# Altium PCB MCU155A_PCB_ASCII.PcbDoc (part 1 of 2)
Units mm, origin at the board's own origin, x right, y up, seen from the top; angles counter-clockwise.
Board outline 32 x 29 mm, 4 copper layers (Top Layer, Layer 1, Layer 2, Bottom Layer), stack 1.567 mm thick; 102 components, 61 nets, 283 pads, 121 vias.
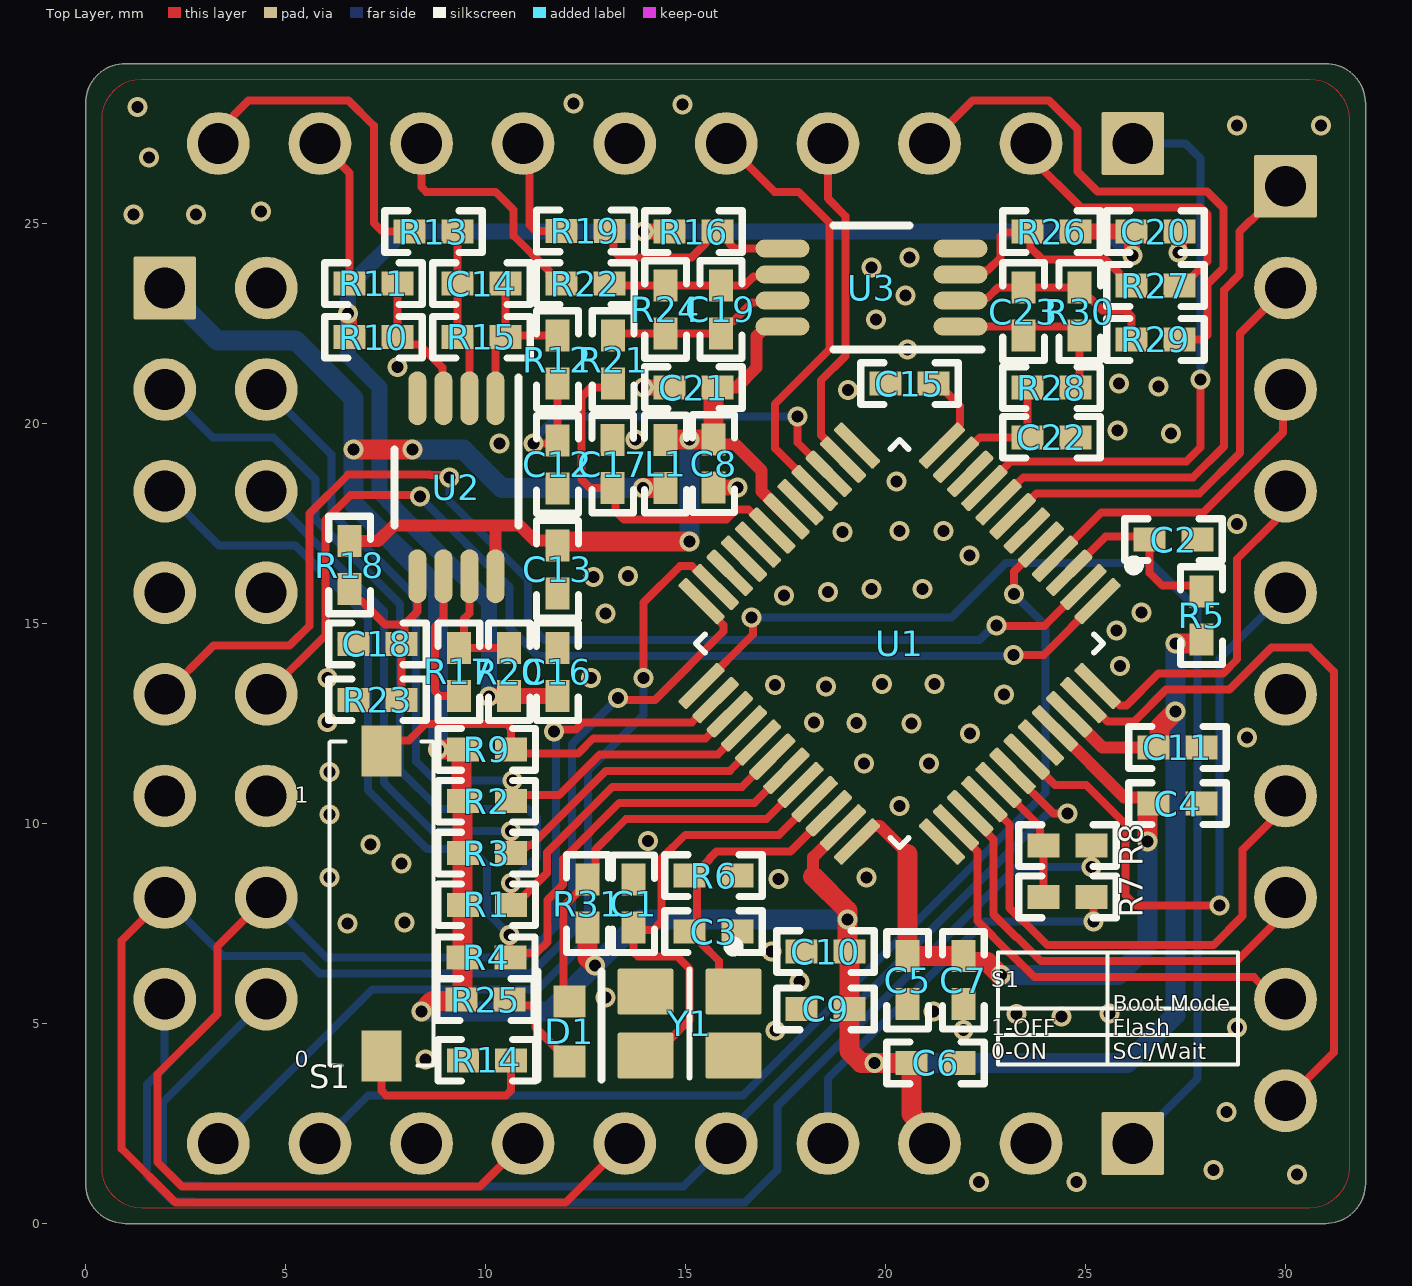
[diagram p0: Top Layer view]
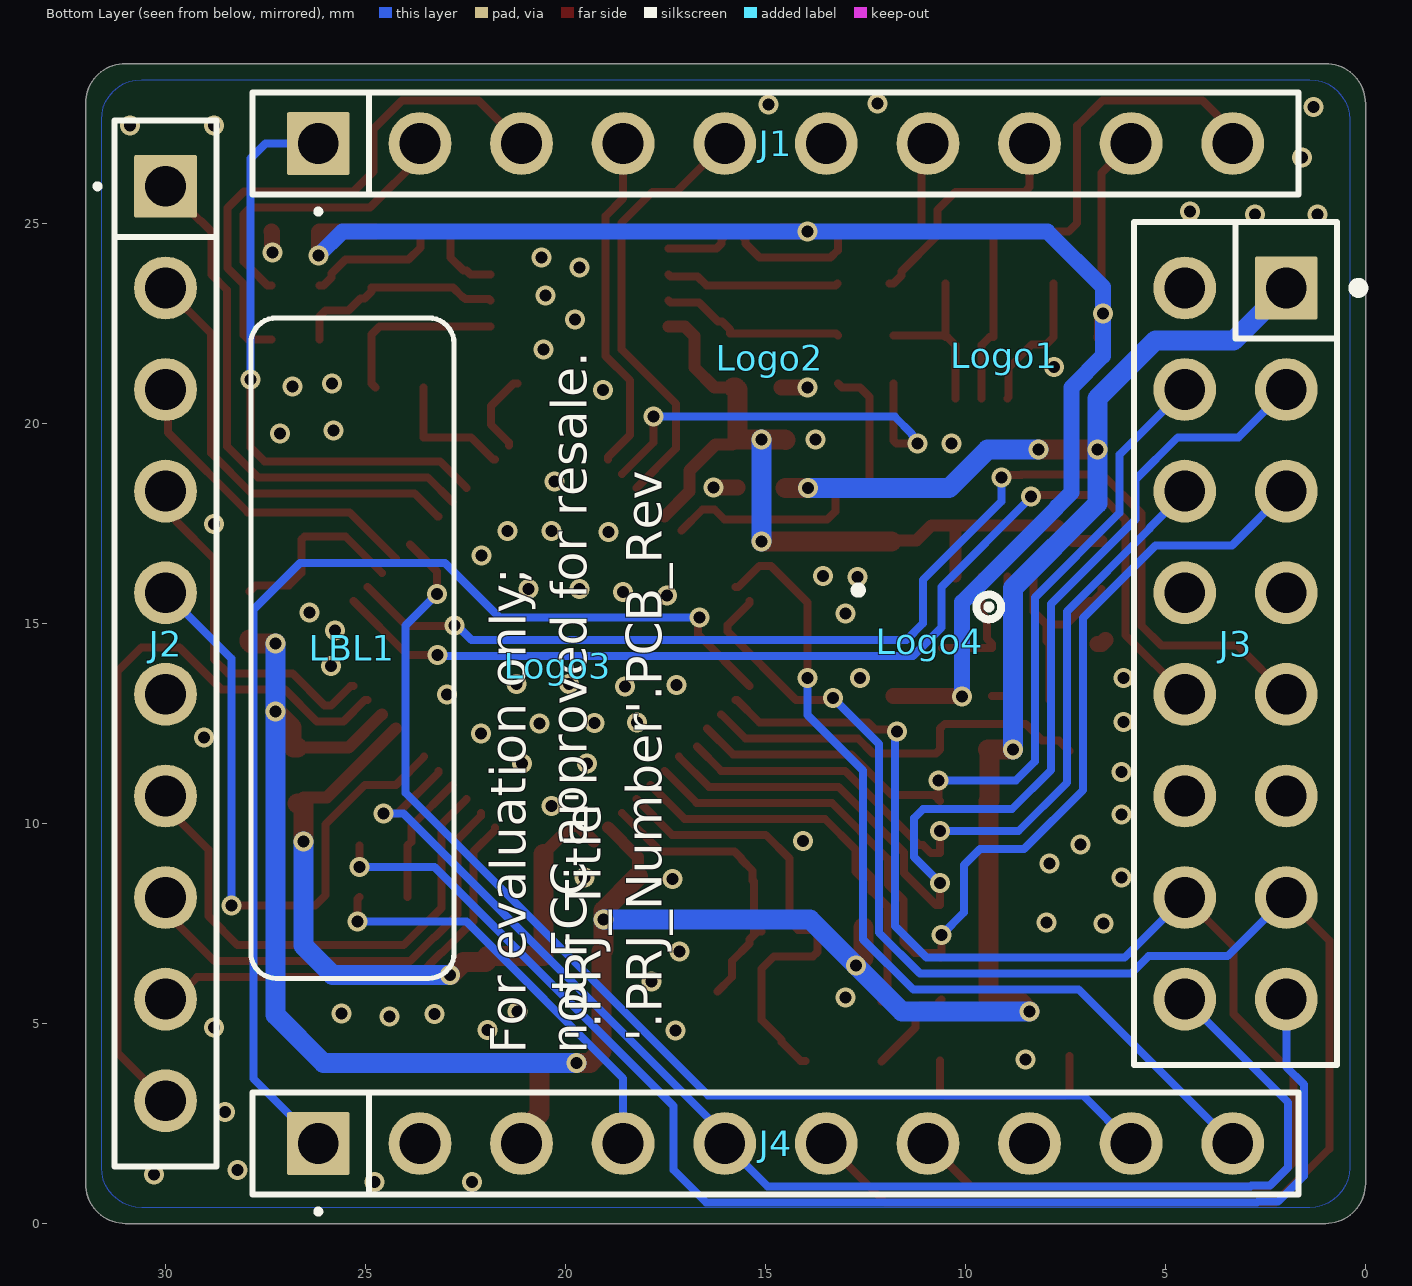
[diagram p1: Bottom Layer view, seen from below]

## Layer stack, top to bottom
Top Solder: solder mask 0.0102, Solder Resist, Dk 3.5
Top Layer: signal copper 0.035
Dielectric 1: prepreg 0.2184, PP-023, Dk 4.5
Layer 1: signal copper 0.035
Dielectric1: core 0.9906, Core-042, Dk 4.6
Layer 2: signal copper 0.035
Dielectric 2: prepreg 0.2184, PP-023, Dk 4.5
Bottom Layer: signal copper 0.035
Bottom Solder: solder mask 0.0102, Solder Resist, Dk 3.5

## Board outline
0,1 0,28 cw(c1,28) 1,29 31,29 cw(c31,28) 32,28 32,1 cw(c31,1) 31,0 1,0 cw(c1,1)

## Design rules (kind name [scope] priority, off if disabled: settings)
AcuteAngle [All] p0: scope1count=1 scope1_0_kind=Board scope1_0_value=Board scope2count=1 scope2_0_kind=Board scope2_0_value=Board commentlength=0 minimum=4.50000000000000E+0001
AcuteAngle [All] p1: minimum=4.50000000000000E+0001 checktracksonly=FALSE
AssemblyTestPointUsage [All] p0: scope1count=1 scope1_0_kind=Board scope1_0_value=Board scope2count=1 scope2_0_kind=Board scope2_0_value=Board commentlength=0
AssemblyTestPointUsage [All] p1: valid=2
AssemblyTestpoint [All] p0: scope1count=1 scope1_0_kind=Board scope1_0_value=Board scope2count=1 scope2_0_kind=Board scope2_0_value=Board commentlength=0
BoardOutlineClearance [All] p0 off: scope1count=1 scope1_0_kind=Board scope1_0_value=Board scope2count=1 scope2_0_kind=Board scope2_0_value=Board commentlength=172 gap=0 // Protel DXP Scope 1 Expression Was: OnCopper and Not InComponentClass('Logo') and not InComponentClass('FiducialMark') and not InRegion(1000,500,4000,800) and not InPoly
BoardOutlineClearance BoardOutlineClearance_Poly [All] p0 off: scope1count=1 scope1_0_kind=Board scope1_0_value=Board scope2count=1 scope2_0_kind=Board scope2_0_value=Board commentlength=58 gap=0 // Protel DXP Scope 1 Expression Was: OnCopper and IsPoly
BoardOutlineClearance BoardOutlineClearance_MountingHoles [All] p0 off: scope1count=1 scope1_0_kind=Board scope1_0_value=Board scope2count=1 scope2_0_kind=Board scope2_0_value=Board commentlength=86 gap=0 // Protel DXP Scope 1 Expression Was: OnCopper and InComponentClass('Mounting Holes')
BoardOutlineClearance BoardOutlineClearance_MountingHoles [OnCopper and InComponentClass('Mounting Holes')] p1: gap=0 ignorepadtopadclearanceinfootprint=FALSE
BoardOutlineClearance BoardOutlineClearance_Poly [OnCopper and IsPoly] p2: gap=0 ignorepadtopadclearanceinfootprint=FALSE
BoardOutlineClearance [OnCopper and Not InComponentClass('Logo') and not InComponentClass('FiducialMark') and not InRegion(1000,500,4000,800) and not InPoly] p3: gap=0 ignorepadtopadclearanceinfootprint=FALSE
Clearance Clearance_1 [All] p0 off: scope1count=1 scope1_0_kind=Board scope1_0_value=Board scope2count=1 scope2_0_kind=Board scope2_0_value=Board commentlength=160 gap=0.19 // Protel DXP Scope 1 Expression Was: (InComponent('J1') or InComponent('J2') or InComponent('J3') or InComponent('J4') ) and not HasFootprint('fiducial10-20')
Clearance [All] p0 off: scope1count=1 scope1_0_kind=Board scope1_0_value=Board scope2count=1 scope2_0_kind=Board scope2_0_value=Board commentlength=159 gap=0.2 // Protel DXP Scope 2 Expression Was: not HasFootprint('fiducial10-20') or (InComponent('J1') or InComponent('J2') or InComponent('J3') or InComponent('J4') )
Clearance SMTPadToTHHole [All] p0 off: scope1count=1 scope1_0_kind=Board scope1_0_value=Board scope2count=1 scope2_0_kind=Board scope2_0_value=Board commentlength=115 gap=0.15 // Protel DXP Scope 2 Expression Was: InSMTComponent and OnLayer('Bottom Layer') and not HasFootprint('TP_SM_1MM')
Clearance PB+ToPB- [All] p0: scope1count=1 scope1_0_kind=NetClass scope1_0_value=HV scope2count=1 scope2_0_kind=NetClass scope2_0_value=LV_Signal commentlength=0 gap=3
Clearance PB+ToACN [All] p0: scope1count=1 scope1_0_kind=NetClass scope1_0_value=V_BUS scope2count=1 scope2_0_kind=NetClass scope2_0_value=ACN commentlength=0 gap=1.5
Clearance PB+ToACL [All] p0: scope1count=1 scope1_0_kind=NetClass scope1_0_value=V_BUS scope2count=1 scope2_0_kind=NetClass scope2_0_value=ACL commentlength=0 gap=3
Clearance PB-ToACL [All] p0: scope1count=1 scope1_0_kind=NetClass scope1_0_value="LV Signal" scope2count=1 scope2_0_kind=NetClass scope2_0_value=ACL commentlength=0 gap=3
Clearance ISOToAll [All] p0 off: scope1count=1 scope1_0_kind=NetClass scope1_0_value=Isolation scope2count=1 scope2_0_kind=Board scope2_0_value=Board commentlength=105 gap=6 // Protel DXP Scope 2 Expression Was: not InNetClass('Isolation')   and (not  OnLayer('Keep-Out Layer'))
Clearance ACLToACN [All] p0: scope1count=1 scope1_0_kind=NetClass scope1_0_value=ACL scope2count=1 scope2_0_kind=NetClass scope2_0_value=ACN commentlength=0 gap=2
Clearance PB-ToACN [All] p0: scope1count=1 scope1_0_kind=NetClass scope1_0_value="LV Signal" scope2count=1 scope2_0_kind=NetClass scope2_0_value=ACN commentlength=0 gap=3
Clearance Clearance_1 [(InComponent('J1') or InComponent('J2') or InComponent('J3') or InComponent('J4') ) and not HasFootprint('fiducial10-20')] p1: gap=0.19 ignorepadtopadclearanceinfootprint=TRUE
Clearance PB+ToPB- [InNetClass('HV') vs InNetClass('LV_Signal')] p2: gap=3 ignorepadtopadclearanceinfootprint=TRUE
Clearance PB-ToACN [InNetClass('LV Signal') vs InNetClass('ACN')] p3: gap=3 ignorepadtopadclearanceinfootprint=TRUE
Clearance ACLToACN [InNetClass('ACL') vs InNetClass('ACN')] p4: gap=2 ignorepadtopadclearanceinfootprint=FALSE
Clearance ISOToAll [InNetClass('Isolation') vs not InNetClass('Isolation')   and (not  OnLayer('Keep-Out Layer'))] p5: gap=6 ignorepadtopadclearanceinfootprint=TRUE
Clearance PB-ToACL [InNetClass('LV Signal') vs InNetClass('ACL')] p6: gap=3 ignorepadtopadclearanceinfootprint=TRUE
Clearance PB+ToACL [InNetClass('V_BUS') vs InNetClass('ACL')] p7: gap=3 ignorepadtopadclearanceinfootprint=TRUE
Clearance PB+ToACN [InNetClass('V_BUS') vs InNetClass('ACN')] p8: gap=1.5 ignorepadtopadclearanceinfootprint=TRUE
Clearance SMTPadToTHHole [not IsVia and OnLayer('Multi-Layer') and not InComponent('J1') and not InComponent('J2') and not InComponent('J3') and not InComponent('J4') and not InComponent('J12') and PadIsPlated vs InSMTComponent and OnLayer('Bottom Layer') and not HasFootprint('TP_SM_1MM')] p9: gap=0.15 ignorepadtopadclearanceinfootprint=FALSE except(3: SMDPad-THPad)
Clearance [All vs not HasFootprint('fiducial10-20') or (InComponent('J1') or InComponent('J2') or InComponent('J3') or InComponent('J4') )] p10: gap=0.2 ignorepadtopadclearanceinfootprint=TRUE
ComponentClearance [All] p0: scope1count=1 scope1_0_kind=Board scope1_0_value=Board scope2count=1 scope2_0_kind=Board scope2_0_value=Board commentlength=0 gap=0.508 collisioncheckmode=3
ComponentClearance ComponentClearance_THtoTH [All] p0 off: scope1count=1 scope1_0_kind=Board scope1_0_value=Board scope2count=1 scope2_0_kind=Board scope2_0_value=Board commentlength=54 gap=0.508 collisioncheckmode=3 // Protel DXP Scope 2 Expression Was: IsThruComponent
ComponentClearance ComponentClearance_THtoSMT [All] p0 off: scope1count=1 scope1_0_kind=Board scope1_0_value=Board scope2count=1 scope2_0_kind=Board scope2_0_value=Board commentlength=53 gap=0.762 collisioncheckmode=3 // Protel DXP Scope 2 Expression Was: IsSMTComponent
ComponentClearance ComponentClearance_SmallPassives [All] p0 off: scope1count=1 scope1_0_kind=Board scope1_0_value=Board scope2count=1 scope2_0_kind=Board scope2_0_value=Board commentlength=508 gap=0.38 collisioncheckmode=3 // Protel DXP Scope 2 Expression Was: HasFootprint('0201*') or HasFootprint('0402*') or HasFootprint('0508') or HasFootprint('0603*') or HasFootprint('0612') or HasFootprint('0805*') or HasFootprint('0815*') or HasFootprint('0830*') or HasFootprint('1206*') or HasFootprint('1210*') or HasFootprint('1808*') or HasFootprint('1812*') or HasFootprint('1825*') or HasFootprint('2010*') or HasFootprint('2220*') or HasFootprint('2225*') or HasFootprint('2512*') or HasFootprint('2728*') or HasFootprint('3518*')
ComponentClearance ComponentClearance_MountingHoles [All] p0: scope1count=1 scope1_0_kind=ComponentClass scope1_0_value="Mounting Holes" scope2count=1 scope2_0_kind=Board scope2_0_value=Board commentlength=0 gap=2.54 collisioncheckmode=3
ComponentClearance ComponentClearance_ScrewToNut [All] p0 off: scope1count=1 scope1_0_kind=Board scope1_0_value=Board scope2count=1 scope2_0_kind=Board scope2_0_value=Board commentlength=71 gap=0.127 collisioncheckmode=3 // Protel DXP Scope 2 Expression Was: (HasFootprint('Keystone_1902C'))
ComponentClearance ComponentClearance_Logo [All] p0: scope1count=1 scope1_0_kind=ComponentClass scope1_0_value=Logo scope2count=1 scope2_0_kind=Board scope2_0_value=Board commentlength=0 gap=0.762 collisioncheckmode=3
ComponentClearance ComponentClearance_Shunt [All] p0: scope1count=1 scope1_0_kind=ComponentClass scope1_0_value=Header scope2count=1 scope2_0_kind=ComponentClass scope2_0_value=Shunt commentlength=0 gap=0 collisioncheckmode=3
ComponentClearance ComponentClearance_MountingHoles_FiducialMarks [All] p0: scope1count=1 scope1_0_kind=ComponentClass scope1_0_value="Mounting Holes" scope2count=1 scope2_0_kind=ComponentClass scope2_0_value=FiducialMark commentlength=0 gap=1.27 collisioncheckmode=3
ComponentClearance ComponentClearance_MountingHoles_FiducialMarks [InComponentClass('Mounting Holes') vs InComponentClass('FiducialMark')] p1: gap=1.27 collisioncheckmode=3 verticalgap=0.254 showdistances=FALSE
ComponentClearance ComponentClearance_Shunt [InComponentClass('Header') vs InComponentClass('Shunt')] p2: gap=0 collisioncheckmode=3 verticalgap=0 showdistances=FALSE
ComponentClearance ComponentClearance_Logo [InComponentClass('Logo')] p3: gap=0.762 collisioncheckmode=3 verticalgap=0.254 showdistances=FALSE
ComponentClearance ComponentClearance_ScrewToNut [(HasFootprint('NY PMS 440 0025 PH')) vs (HasFootprint('Keystone_1902C'))] p4: gap=0.127 collisioncheckmode=3 verticalgap=0.254 showdistances=FALSE
ComponentClearance ComponentClearance_MountingHoles [InComponentClass('Mounting Holes')] p5: gap=2.54 collisioncheckmode=3 verticalgap=2540 showdistances=FALSE
ComponentClearance ComponentClearance_SmallPassives [HasFootprint('0201*') or HasFootprint('0402*') or HasFootprint('0508') or HasFootprint('0603*') or HasFootprint('0612') or HasFootprint('0805*') or HasFootprint('0815*') or HasFootprint('0830*') or HasFootprint('1206*') or HasFootprint('1210*') or HasFootprint('1808*') or HasFootprint('1812*') or HasFootprint('1825*') or HasFootprint('2010*') or HasFootprint('2220*') or HasFootprint('2225*') or HasFootprint('2512*') or HasFootprint('2728*') or HasFootprint('3518*') vs HasFootprint('0201*') or HasFootprint('0402*') or HasFootprint('0508') or HasFootprint('0603*') or HasFootprint('0612') or HasFootprint('0805*') or HasFootprint('0815*') or HasFootprint('0830*') or HasFootprint('1206*') or HasFootprint('1210*') or HasFootprint('1808*') or HasFootprint('1812*') or HasFootprint('1825*') or HasFootprint('2010*') or HasFootprint('2220*') or HasFootprint('2225*') or HasFootprint('2512*') or HasFootprint('2728*') or HasFootprint('3518*')] p6: gap=0.38 collisioncheckmode=3 verticalgap=0.254 showdistances=FALSE
ComponentClearance ComponentClearance_THtoSMT [IsThruComponent vs IsSMTComponent] p7: gap=0.762 collisioncheckmode=3 verticalgap=0.762 showdistances=FALSE
ComponentClearance ComponentClearance_THtoTH [IsThruComponent vs IsThruComponent] p8: gap=0.508 collisioncheckmode=3 verticalgap=0.762 showdistances=FALSE
ComponentClearance [All] p9: gap=0.508 collisioncheckmode=3 verticalgap=0.254 showdistances=FALSE
DiffPairsRouting [All] p0: scope1count=1 scope1_0_kind=Board scope1_0_value=Board scope2count=1 scope2_0_kind=Board scope2_0_value=Board commentlength=0
DiffPairsRouting [All] p1: maxlimit=2.54 minlimit=0.254 mostfreqgap=0.254 toplayer_minwidth=0.381 toplayer_maxwidth=0.381 toplayer_prefwidth=0.381 midlayer1_minwidth=0.381 midlayer1_maxwidth=0.381 midlayer1_prefwidth=0.381 midlayer2_minwidth=0.381 midlayer2_maxwidth=0.381 midlayer2_prefwidth=0.381 bottomlayer_minwidth=0.381 bottomlayer_maxwidth=0.381 bottomlayer_prefwidth=0.381 maxuncoupledlength=25.4
FabricationTestPointUsage TestPointUsage [All] p0: scope1count=1 scope1_0_kind=Board scope1_0_value=Board scope2count=1 scope2_0_kind=Board scope2_0_value=Board commentlength=0 valid=2 allowmultiple=FALSE
FabricationTestPointUsage TestPointUsage [All] p1: valid=2 allowmultiple=FALSE
FabricationTestpoint Testpoint [All] p0: scope1count=1 scope1_0_kind=Board scope1_0_value=Board scope2count=1 scope2_0_kind=Board scope2_0_value=Board commentlength=0 side=3 testpointundercomponent=TRUE minsize=1.016 maxsize=2.54 preferedsize=1.524 minholesize=0 maxholesize=1.016 preferedholesize=0.813 testpointgrid=0.025
FabricationTestpoint Testpoint [All] p1: side=3 testpointundercomponent=TRUE minsize=1.016 maxsize=2.54 preferedsize=1.524 minholesize=0 maxholesize=1.016 preferedholesize=0.813 testpointgrid=0.025 allowsidetop=TRUE allowsidebottom=TRUE usegrid=TRUE gridtolerance=0
FanoutControl Fanout_Small [All] p0 off: scope1count=1 scope1_0_kind=Board scope1_0_value=Board scope2count=1 scope2_0_kind=Board scope2_0_value=Board commentlength=84 // Protel DXP Scope 1 Expression Was: (CompPinCount < 5)   Fanout_Small (Default Rule)
FanoutControl Fanout_Default [All] p0: scope1count=1 scope1_0_kind=Board scope1_0_value=Board scope2count=1 scope2_0_kind=Board scope2_0_value=Board commentlength=30 // Fanout_Default (Default Rule)
FanoutControl Fanout_SOIC [All] p0 off: scope1count=1 scope1_0_kind=Board scope1_0_value=Board scope2count=1 scope2_0_kind=Board scope2_0_value=Board commentlength=71 // Protel DXP Scope 1 Expression Was: IsSOIC   Fanout_SOIC (Default Rule)
FanoutControl Fanout_BGA [All] p0 off: scope1count=1 scope1_0_kind=Board scope1_0_value=Board scope2count=1 scope2_0_kind=Board scope2_0_value=Board commentlength=69 // Protel DXP Scope 1 Expression Was: IsBGA   Fanout_BGA (Default Rule)
FanoutControl Fanout_LCC [All] p0 off: scope1count=1 scope1_0_kind=Board scope1_0_value=Board scope2count=1 scope2_0_kind=Board scope2_0_value=Board commentlength=69 // Protel DXP Scope 1 Expression Was: IsLCC   Fanout_LCC (Default Rule)
FanoutControl Fanout_LCC [IsLCC] p1: bgadir=Out bgaviamode=Centered fanoutstyle=Auto fanoutdirection=Alternating viagrid=0.025 // Fanout_LCC (Default Rule)
FanoutControl Fanout_BGA [IsBGA] p2: bgadir=Out bgaviamode=Centered fanoutstyle=Auto fanoutdirection=Alternating viagrid=0.025 // Fanout_BGA (Default Rule)
FanoutControl Fanout_Default [All] p4: bgadir=Out bgaviamode=Centered fanoutstyle=Auto fanoutdirection=Alternating viagrid=0.025 // Fanout_Default (Default Rule)
FanoutControl Fanout_Small [(CompPinCount < 5)] p5: bgadir=Out bgaviamode=Centered fanoutstyle=Auto fanoutdirection=OutThenIn viagrid=0.025 // Fanout_Small (Default Rule)
Height [All] p0: scope1count=1 scope1_0_kind=Board scope1_0_value=Board scope2count=1 scope2_0_kind=Board scope2_0_value=Board commentlength=0
HoleSize [All] p0: scope1count=1 scope1_0_kind=Board scope1_0_value=Board scope2count=1 scope2_0_kind=Board scope2_0_value=Board commentlength=0 absolutevalues=TRUE maxlimit=6.375 minlimit=0.2 maxpercent=80.000 minpercent=20.000
HoleSize [All] p1: absolutevalues=TRUE maxlimit=6.375 minlimit=0.2 maxpercent=80.000 minpercent=20.000
HoleToHoleClearance [All] p0: scope1count=1 scope1_0_kind=Board scope1_0_value=Board scope2count=1 scope2_0_kind=Board scope2_0_value=Board commentlength=0
LayerPairs [All] p0: scope1count=1 scope1_0_kind=Board scope1_0_value=Board scope2count=1 scope2_0_kind=Board scope2_0_value=Board commentlength=0 enforce=TRUE
MinimumAnnularRing [All] p0: scope1count=1 scope1_0_kind=Board scope1_0_value=Board scope2count=1 scope2_0_kind=Board scope2_0_value=Board commentlength=0 minimumring=0.2
MinimumAnnularRing MinimumAnnularRing_ThermalPadVias [All] p0 off: scope1count=1 scope1_0_kind=Board scope1_0_value=Board scope2count=1 scope2_0_kind=Board scope2_0_value=Board commentlength=63 minimumring=0.15 // Protel DXP Scope 1 Expression Was: IsVia and InAnyComponent
MinimumAnnularRing MinimumAnnularRing_ThermalPadVias [IsVia and InAnyComponent] p1: minimumring=0.15
MinimumAnnularRing [All] p2: minimumring=0.2
MinimumSolderMaskSliver [All] p0: scope1count=1 scope1_0_kind=Board scope1_0_value=Board scope2count=1 scope2_0_kind=Board scope2_0_value=Board commentlength=0
MinimumSolderMaskSliver MinimumSolderMaskSliver_Logo [All] p0: scope1count=1 scope1_0_kind=ComponentClass scope1_0_value=Logo scope2count=1 scope2_0_kind=ComponentClass scope2_0_value=Logo commentlength=0
MinimumSolderMaskSliver MinimumSolderMaskSliver_Logo [InComponentClass('Logo') vs InComponentClass('Logo')] p1: minsoldermaskwidth=0.018
MinimumSolderMaskSliver [All] p2: minsoldermaskwidth=0.1
NetAntennae [All] p0: scope1count=1 scope1_0_kind=Board scope1_0_value=Board scope2count=1 scope2_0_kind=Board scope2_0_value=Board commentlength=0
PasteMaskExpansion [All] p0: scope1count=1 scope1_0_kind=Board scope1_0_value=Board scope2count=1 scope2_0_kind=Board scope2_0_value=Board commentlength=0 expansion=0
PlaneClearance [All] p0: scope1count=1 scope1_0_kind=Board scope1_0_value=Board scope2count=1 scope2_0_kind=Board scope2_0_value=Board commentlength=0 clearance=0.508
PlaneConnect [All] p0: scope1count=1 scope1_0_kind=Board scope1_0_value=Board scope2count=1 scope2_0_kind=Board scope2_0_value=Board commentlength=0 planeconnectstyle=Direct reliefexpansion=0.254 reliefentries=4 reliefconductorwidth=0.254 reliefairgap=0.254
PlaneConnect [All] p1: planeconnectstyle=Direct reliefexpansion=0.254 reliefentries=4 reliefconductorwidth=0.254 reliefairgap=0.254
PolygonConnect "Thermal relief" [All] p0 off: scope1count=1 scope1_0_kind=Board scope1_0_value=Board scope2count=1 scope2_0_kind=Board scope2_0_value=Board commentlength=89 connectstyle=Relief reliefconductorwidth=0.5 reliefentries=4 polygonreliefangle="90 Angle" // Protel DXP Scope 2 Expression Was: InNet('GND') or innet('GND_ISO')  or innet('ubus')
PolygonConnect [All] p0: scope1count=1 scope1_0_kind=Board scope1_0_value=Board scope2count=1 scope2_0_kind=Board scope2_0_value=Board commentlength=0 connectstyle=Direct reliefconductorwidth=0.254 reliefentries=4 polygonreliefangle="90 Angle"
PolygonConnect "Thermal relief" [All vs InNet('GND') or innet('GND_ISO')  or innet('ubus')] p1: thpad.connectstyle=Relief thpad.reliefconductorwidth=0.5 thpad.reliefentries=4 thpad.polygonreliefangle="90 Angle" thpad.airgapwidth=0.254 smdpad.connectstyle=Direct smdpad.reliefconductorwidth=0.5 smdpad.reliefentries=4 smdpad.polygonreliefangle="90 Angle" smdpad.airgapwidth=0.254 via.connectstyle=Direct via.reliefconductorwidth=0.5 via.reliefentries=4 via.polygonreliefangle="90 Angle" via.airgapwidth=0.254
PolygonConnect [All] p2: connectstyle=Direct reliefconductorwidth=0.254 reliefentries=4 polygonreliefangle="90 Angle" airgapwidth=0.254
RoutingCorners [All] p0: scope1count=1 scope1_0_kind=Board scope1_0_value=Board scope2count=1 scope2_0_kind=Board scope2_0_value=Board commentlength=0 cornerstyle=45-Degree minsetback=2.54 maxsetback=2.54
RoutingLayers [All] p0: scope1count=1 scope1_0_kind=Board scope1_0_value=Board scope2count=1 scope2_0_kind=Board scope2_0_value=Board commentlength=0 top layer=Automatic mid layer 1=Automatic mid layer 2=Automatic bottom layer=Automatic
RoutingPriority [All] p0: scope1count=1 scope1_0_kind=Board scope1_0_value=Board scope2count=1 scope2_0_kind=Board scope2_0_value=Board commentlength=0
RoutingTopology [All] p0: scope1count=1 scope1_0_kind=Board scope1_0_value=Board scope2count=1 scope2_0_kind=Board scope2_0_value=Board commentlength=0 topology=Shortest
RoutingVias [All] p0: scope1count=1 scope1_0_kind=Board scope1_0_value=Board scope2count=1 scope2_0_kind=Board scope2_0_value=Board commentlength=0 holewidth=0.2 width=0.5 viastyle="Through Hole" minholewidth=0.2 minwidth=0.4 maxholewidth=1 maxwidth=1.4
RoutingVias ThermalPadVias [All] p0 off: scope1count=1 scope1_0_kind=Board scope1_0_value=Board scope2count=1 scope2_0_kind=Board scope2_0_value=Board commentlength=63 holewidth=0.2 width=0.5 viastyle="Through Hole" minholewidth=0.2 minwidth=0.5 maxholewidth=0.33 maxwidth=0.6 // Protel DXP Scope 1 Expression Was: IsVia and InAnyComponent
RoutingVias ThermalPadVias [IsVia and InAnyComponent] p1: holewidth=0.2 width=0.5 viastyle="Through Hole" minholewidth=0.2 minwidth=0.5 maxholewidth=0.33 maxwidth=0.6
RoutingVias [All] p2: holewidth=0.2 width=0.5 viastyle="Through Hole" minholewidth=0.2 minwidth=0.4 maxholewidth=1 maxwidth=1.4
ShortCircuit [All] p0: scope1count=1 scope1_0_kind=Board scope1_0_value=Board scope2count=1 scope2_0_kind=Board scope2_0_value=Board commentlength=0 allowed=FALSE
SilkToBoardRegionClearance [All] p0 off: scope1count=1 scope1_0_kind=Board scope1_0_value=Board scope2count=1 scope2_0_kind=Board scope2_0_value=Board commentlength=130 // Protel DXP Scope 1 Expression Was: Not ((IsComment or IsDesignator) And (Hide <> 'False')) and not InRegion(1000,500,4000,800)
SilkToBoardRegionClearance [Not ((IsComment or IsDesignator) And (Hide <> 'False')) and not InRegion(1000,500,4000,800)] p1:
SilkToSilkClearance [All] p0: scope1count=1 scope1_0_kind=Board scope1_0_value=Board scope2count=1 scope2_0_kind=Board scope2_0_value=Board commentlength=0
SilkToSilkClearance SilkToSilkClearance_Pb-FreeLogo [All] p0 off: scope1count=1 scope1_0_kind=Board scope1_0_value=Board scope2count=1 scope2_0_kind=Board scope2_0_value=Board commentlength=120 // Protel DXP Scope 2 Expression Was: (HasFootprint('Pb-Free_Overlay_Medium') OR HasFootprint('Pb-Free_Overlay_Small'))
SilkToSilkClearance SilkToSilkClearance_Pb-FreeLogo [(HasFootprint('Pb-Free_Overlay_Medium') OR HasFootprint('Pb-Free_Overlay_Small')) vs (HasFootprint('Pb-Free_Overlay_Medium') OR HasFootprint('Pb-Free_Overlay_Small'))] p1: silktosilkclearance=0
SilkToSilkClearance [All] p2: silktosilkclearance=0.1
SilkToSolderMaskClearance "Silk to Solder Mask Opening" [All] p0: scope1count=1 scope1_0_kind=Board scope1_0_value=Board scope2count=1 scope2_0_kind=Board scope2_0_value=Board commentlength=0
SilkToSolderMaskClearance SilkToComponentPadClearance [All] p0 off: scope1count=1 scope1_0_kind=Board scope1_0_value=Board scope2count=1 scope2_0_kind=Board scope2_0_value=Board commentlength=87 // Protel DXP Scope 1 Expression Was: (IsPad or IsFill or IsRegion) and InAnycomponent
SilkToSolderMaskClearance SilkToComponentPadClearance [(IsPad or IsFill or IsRegion) and InAnycomponent] p1: minsilkscreentomaskgap=0.127 clearancetoexposedcopper=TRUE
SilkToSolderMaskClearance "Silk to Solder Mask Opening" [All] p2: minsilkscreentomaskgap=0.1 clearancetoexposedcopper=FALSE
SolderMaskExpansion [All] p0: scope1count=1 scope1_0_kind=Board scope1_0_value=Board scope2count=1 scope2_0_kind=Board scope2_0_value=Board commentlength=0 expansion=0.05
SolderMaskExpansion [All] p1: expansion=0.05 istentingtop=FALSE
UnRoutedNet [All] p0: scope1count=1 scope1_0_kind=Board scope1_0_value=Board scope2count=1 scope2_0_kind=Board scope2_0_value=Board commentlength=0
UnRoutedNet [All] p1: checkbadconnections=TRUE
UnpouredPolygon [All] p0: scope1count=1 scope1_0_kind=Board scope1_0_value=Board scope2count=1 scope2_0_kind=Board scope2_0_value=Board commentlength=0
Width [All] p0: scope1count=1 scope1_0_kind=Board scope1_0_value=Board scope2count=1 scope2_0_kind=Board scope2_0_value=Board commentlength=0 maxlimit=5 minlimit=0.2 preferedwidth=0.3
Width [All] p1: maxlimit=5 minlimit=0.2 preferedwidth=0.3 minimp=50.000000 maximp=50.000000 favimp=50.000000 checkconnectedcopper=TRUE
14 further rules are at their usual default settings.

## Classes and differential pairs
component class Logo: Logo2
component class Label: LBL1
component class MCU155A_Full: C1 C2 C3 C4 C5 C6 C7 C8 C9 C10 C11 C12 C13 C14 C15 C16 C17 C18 C19 C20 C21 C22 C23 D1 J1 J2 J3 J4 L1 LBL1 Logo1 Logo2 Logo3 Logo4 R1 R2 R3 R4 R5 R6 R7 R8 R9 R10 R11 R12 R13 R14 R15 R16 R17 R18 R19 R20 R21 R22 R23 R24 R25 R26 R27 R28 R29 R30 R31 S1 U1 U2 U3 Y1

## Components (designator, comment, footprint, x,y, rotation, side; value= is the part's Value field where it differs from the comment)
C1 "GRM1555C1H120JA01D" 0402 13.7,7.998 r270 top
C2 "GRM155R71C104KA88D" 0402 27.2,17.1 r0 top
C3 "GRM1555C1H120JA01D" 0402 15.7,7.3 r0 top
C4 "GRM155R71C104KA88D" 0402 27.3,10.5 r180 top
C5 "GRM155R71C104KA88D" 0402 20.551,6.083 r90 top
C6 "GRM155R61A106ME11" 0402 21.25,4.015 r0 top
C7 "GRM155R61A106ME11" 0402 21.948,6.083 r90 top
C8 "GRM155R61A106ME11" 0402 15.7,19 r270 top
C9 "GRM155R61A106ME11" 0402 18.5,5.366 r180 top
C10 "GRM155R71C104KA88D" 0402 18.5,6.8 r180 top
C11 "GRM155R71C104KA88D" 0402 27.3,11.901 r0 top
C12 "C1005C0G1H221F050BA" 0402 11.8,18.977 r270 top
C13 "GRM155R71C104KA88D" 0402 11.8,16.353 r270 top
C14 "GRM1555C1H101JA01D" 0402 9.9,23.5 r0 top
C15 "GRM155R61A225ME95" 0402 20.6,21 r180 top
C16 "GRM155R61C103KA01D" 0402 11.799,13.793 r90 top
C17 "C1005C0G1H221F050BA" 0402 13.18,18.988 r90 top
C18 "GRM155R71C104KA88D" 0402 7.299,14.491 r180 top
C19 "GRM1555C1H101JA01D" 0402 15.887,22.852 r270 top
C20 "GRM155R71C104KA88D" 0402 26.75,24.8 r0 top
C21 "GRM155R71C104KA88D" 0402 15.2,20.9 r180 top
C22 "C1005C0G1H221F050BA" 0402 24.15,19.656 r0 top
C23 "GRM1555C1H101JA01D" 0402 23.451,22.8 r270 top
D1 "LTST-C193KRKT-5A" LTST-C193_Red 12.1,4.8 r90 top
J1 "SSQ-110-03-T-S" FP-SSQ-110-03-T-S_CONN_RCPT10-MFG 14.75,27 r180 bottom
J2 "SSQ-110-03-T-S" FP-SSQ-110-03-T-S_CONN_RCPT10-MFG 30,14.5 r270 bottom locked
J3 "SSQ-108-03-T-D" FP-SSQ-108-03-T-D_HDR16-MFG 3.25,14.5 r270 bottom locked
J4 "SSQ-110-03-T-S" FP-SSQ-110-03-T-S_CONN_RCPT10-MFG 14.75,2 r180 bottom locked
L1 "782423100" 0402 14.5,18.988 r90 top
LBL1 "THT-14-423-10" Label_650x200 25.326,14.385 r270 bottom
Logo1 "CE Mark" CE_Mark_5mm 9.033,21.7 r90 bottom
Logo2 "Texas Instruments" TI_Symbol_Overlay_Small 14.9,21.65 r90 bottom
Logo3 "FCC disclaimer" FCC_disclaimer_stacked 20.2,13.95 r90 bottom
Logo4 "WEEE logo" WEEE_Minimum 10.9,14.55 r90 bottom
M44 "Comment" Arrow 375.549,113.9 r0 top
M45 "Comment" Arrow 418.549,113.9 r180 bottom
M46 "Comment" MARK 448.049,-5.6 r0 top
M47 "Comment" Toolinghole 433.049,-7.1 r0 top
M48 "Comment" "White oil-26X4" 354.049,111.9 r0 top
M49 "Comment" "Bad Mark" 418.049,-5.6 r0 top
M49 "Comment" MARK 443.049,-5.6 r0 top
M49_1 "Comment" "Bad Mark" 386.049,-5.6 r0 top
M49_2 "Comment" "Bad Mark" 354.049,-5.6 r0 top
M50 "Comment" MARK 298.049,-5.6 r0 top
M51 "Comment" MARK 298.049,112.4 r0 top
M52 "Comment" MARK 448.049,112.4 r0 top
M53 "Comment" Toolinghole 308.049,-7.1 r0 top
M54 "Comment" Toolinghole 308.049,113.9 r0 top
M55 "Comment" Toolinghole 438.049,113.9 r0 top
M56 "Comment" "Bad Mark" 413.049,-5.6 r0 top
M56_1 "Comment" "Bad Mark" 381.049,-5.6 r0 top
M56_2 "Comment" "Bad Mark" 349.049,-5.6 r0 top
M57 "Comment" "Bad Mark" 408.049,-5.6 r0 top
M57_1 "Comment" "Bad Mark" 376.049,-5.6 r0 top
M57_2 "Comment" "Bad Mark" 344.049,-5.6 r0 top
M57_2_1 "Comment" "Bad Mark" 334.049,-5.6 r0 top
M57_2_2 "Comment" "Bad Mark" 322.049,-5.6 r0 top
M58 "Comment" "Bad Mark" 403.049,-5.6 r0 top
M58_1 "Comment" "Bad Mark" 371.049,-5.6 r0 top
M58_2 "Comment" "Bad Mark" 339.049,-5.6 r0 top
M58_2_1 "Comment" "Bad Mark" 329.049,-5.6 r0 top
M59 "Comment" "Bad Mark" 398.049,-5.6 r0 top
M59_1 "Comment" "Bad Mark" 366.049,-5.6 r0 top
M60 "Comment" "Bad Mark" 393.049,-5.6 r0 top
M60_1 "Comment" "Bad Mark" 361.049,-5.6 r0 top
M61 "Comment" "Bad Mark" 425.049,-5.6 r0 top
R1 "ERJ-2RKF2401X" 0402 10.035,7.967 r180 top
R2 "RC0402FR-0710KL" 0402 10.035,10.557 r180 top
R3 "RC0402FR-0710KL" 0402 10.035,9.262 r180 top
R4 "RC0402FR-0710KL" 0402 10.019,6.647 r180 top
R5 "RC0402FR-0710KL" 0402 27.9,15.2 r270 top
R6 "RG1005P-104-B-T5" 0402 15.7,8.698 r180 top
R7 "RC0402JR-070RL" 0402 24.55,8.166 r180 top
R8 "RC0402JR-070RL" 0402 24.55,9.45 r180 top
R9 "CMP-0026949-3" 0402 10.035,11.852 r180 top
R10 "RC0402FR-0710KL" 0402 7.2,22.158 r180 top
R11 "ERJ-2RKF2401X" 0402 7.2,23.5 r0 top
R12 "RC0402FR-07100RL" 0402 11.8,21.6 r270 top
R13 "ERJ-2RKF2401X" 0402 8.7,24.8 r0 top
R14 "CMP-0026890-5" 0402 10.035,4.082 r180 top
R15 "RC0402FR-0710KL" 0402 9.9,22.158 r0 top
R16 "RC0402FR-0710KL" 0402 15.2,24.8 r180 top
R17 "RC0402FR-0710KL" 0402 9.336,13.793 r270 top
R18 "RC0402FR-0710KL" 0402 6.6,16.463 r90 top
R19 "ERJ-2RKF2401X" 0402 12.498,24.814 r0 top
R20 "RC0402FR-07100RL" 0402 10.592,13.793 r270 top
R21 "RC0402FR-07100RL" 0402 13.189,21.6 r270 top
R22 "ERJ-2RKF2401X" 0402 12.498,23.5 r0 top
R23 "RC0402FR-0710KL" 0402 7.3,13.094 r0 top
R24 "RC0402FR-0710KL" 0402 14.501,22.852 r270 top
R25 "RC0402FR-071KL" 0402 10,5.6 r0 top
R26 "RC0402FR-0710KL" 0402 24.15,24.8 r0 top
R27 "ERJ-2RKF2401X" 0402 26.75,23.451 r180 top
R28 "RC0402FR-07100RL" 0402 24.15,20.9 r180 top
R29 "ERJ-2RKF2401X" 0402 26.75,22.102 r180 top
R30 "RC0402FR-0710KL" 0402 24.853,22.8 r270 top
R31 "CMP-0026949-3" 0402 12.55,8 r270 top
S1 "CHS-01TB" SW_CHS-01TB 7.4,8 r0 top
U1 "F2800137PT" PT0048A-MFG 20.35,14.5 r225 top locked
U2 "TLV9062IDGKR" DGK0008A_N 9.273,18.406 r270 top
U3 "TLV9062IDGKR" DGK0008A_N 19.65,23.4 r180 top
Y1 "830108207209" FP-830108207209_SMT_CRYSTAL_3MM2_2MM5-MFG 15.1,5 r180 top

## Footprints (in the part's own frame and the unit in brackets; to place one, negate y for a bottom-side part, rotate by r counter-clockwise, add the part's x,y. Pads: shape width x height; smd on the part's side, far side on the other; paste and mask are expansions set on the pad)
0402 [mm] "0402 from SM-752 data"
  rect 0.8x0.6 smd: 1(-0.6,0) 2(0.6,0)
  silkscreen extent -1.22,-0.52 1.22,0.52
Arrow [mm] "·½Ïò¼ýÍ·"
"Bad Mark" [mm]
  round 2 on Bottom Solder: 2(0,0)
  round 2 on Top Solder: 2(0,0)
CE_Mark_5mm [mm] "Minimum text height for CE Mark"
DGK0008A_N [mm] "TSOP, 8-Leads, Body 3x3mm, Pitch 0.65mm, IPC Medium Density"
  oval 1.35x0.45 smd: 1(-2.225,0.975) 2(-2.225,0.325) 3(-2.225,-0.325) 4(-2.225,-0.975) 5(2.225,-0.975) 6(2.225,-0.325) 7(2.225,0.325) 8(2.225,0.975)
  silkscreen extent -2.75,-1.55 0.95,1.55
FCC_disclaimer_stacked [mm]
FP-830108207209_SMT_CRYSTAL_3MM2_2MM5-MFG [mm]
  rrect9% 1.4x1.15 smd paste+0 mask+0: 1(-1.1,-0.8) 2(1.1,-0.8) 3(1.1,0.8) 4(-1.1,0.8)
  silkscreen extent -1.23,-2.05 0,1.35
FP-SSQ-108-03-T-D_HDR16-MFG [mm]
  rrect6% 1.57x1.57 hole 1.02 paste+0 mask+0: 1(-8.89,1.27)
  round 1.57 hole 1.02 paste+0 mask+0: 2(-8.89,-1.27) 3(-6.35,1.27) 4(-6.35,-1.27) 5(-3.81,1.27) 6(-3.81,-1.27) 7(-1.27,1.27) 8(-1.27,-1.27) 9(1.27,1.27) 10(1.27,-1.27) 11(3.81,1.27) 12(3.81,-1.27) 13(6.35,1.27) 14(6.35,-1.27) 15(8.89,1.27) 16(8.89,-1.27)
  silkscreen extent -10.54,-2.54 10.54,3.19
FP-SSQ-110-03-T-S_CONN_RCPT10-MFG [mm]
  rrect6% 1.57x1.57 hole 1.02 paste+0 mask+0: 1(-11.43,0)
  round 1.57 hole 1.02 paste+0 mask+0: 2(-8.89,0) 3(-6.35,0) 4(-3.81,0) 5(-1.27,0) 6(1.27,0) 7(3.81,0) 8(6.35,0) 9(8.89,0) 10(11.43,0)
  silkscreen extent -13.08,-1.76 13.08,1.27
Label_650x200 [mil] "Thermal Transfer Label"
  round 1 on Mech14: 0(0,0)
  silkscreen extent -325,-100 325,100
LTST-C193_Red [mm] "SMD, 2-Leads, Body1.6x0.8mm"
  rect 0.8x0.8 smd: 1(-0.75,0) 2(0.75,0)
  silkscreen extent -1.2,-0.8 1.5,0.8
MARK [mm]
  round 1 smd mask+0: 1(0,0)
  round 1 smd far side mask+0: 2(0,0)
PT0048A-MFG [mm]
  rrect33% 1.4x0.3 smd paste-1000 mask+0: 1(-4.25,2.75) 2(-4.25,2.25) 3(-4.25,1.75) 4(-4.25,1.25) 5(-4.25,0.75) 6(-4.25,0.25) 7(-4.25,-0.25) 8(-4.25,-0.75) 9(-4.25,-1.25) 10(-4.25,-1.75) 11(-4.25,-2.25) 12(-4.25,-2.75) 25(4.25,-2.75) 26(4.25,-2.25) 27(4.25,-1.75) 28(4.25,-1.25) 29(4.25,-0.75) 30(4.25,-0.25) 31(4.25,0.25) 32(4.25,0.75) 33(4.25,1.25) 34(4.25,1.75) 35(4.25,2.25) 36(4.25,2.75)
  rrect33% 0.3x1.4 smd paste-1000 mask+0: 13(-2.75,-4.25) 14(-2.25,-4.25) 15(-1.75,-4.25) 16(-1.25,-4.25) 17(-0.75,-4.25) 18(-0.25,-4.25) 19(0.25,-4.25) 20(0.75,-4.25) 21(1.25,-4.25) 22(1.75,-4.25) 23(2.25,-4.25) 24(2.75,-4.25) 37(2.75,4.25) 38(2.25,4.25) 39(1.75,4.25) 40(1.25,4.25) 41(0.75,4.25) 42(0.25,4.25) 43(-0.25,4.25) 44(-0.75,4.25) 45(-1.25,4.25) 46(-1.75,4.25) 47(-2.25,4.25) 48(-2.75,4.25)
  silkscreen extent -5.65,-3.6 3.6,3.6
SW_CHS-01TB [mm] "CHS Recommended footprint"
  rect 1x1.27 smd: 1(0,3.81) 2(0,-3.81)
  silkscreen extent -1.3,-4.05 1.3,4.05
TI_Symbol_Overlay_Small [mm]
Toolinghole [mm]
  round 2 hole 2 unplated: 1(0,0)
  silkscreen extent -1.41,-1.41 1.41,1.41
WEEE_Minimum [mm] "WEEElie bin"
  silkscreen extent 0.56,-1.79 1.38,1.88
"White oil-26X4" [mm] "¶þÎ¬Âë°×ÓÍ¿ò"
  silkscreen extent -26,0 0,4

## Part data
C1 C3: library part CMP-0006415-2, "CAP, CERM, 12 pF, 50 V, +/- 5%, C0G/NP0, 0402"
C2 C4 C5 C10 C11 C13 C18 C20 C21: library part CMP-0006641-2, "CAP, CERM, 0.1 uF, 16 V, +/- 10%, X7R, 0402"
C6 C7 C8 C9: library part CMP-0006564-1, "CAP, CERM, 10 uF, 10 V, +/- 20%, X5R, 0402"
C12 C17 C22: library part CMP-0006249-2, "CAP, CERM, 220 pF, 50 V, +/- 1%, C0G/NP0, 0402"
C14 C19 C23: library part CMP-0006410-2, "CAP, CERM, 100 pF, 50 V, +/- 5%, C0G/NP0, 0402"
C15: library part CMP-0006571-2, "CAP, CERM, 2.2 uF, 10 V, +/- 20%, X5R, 0402"
C16: library part CMP-0006590-2, "CAP, CERM, 0.01 uF, 16 V, +/- 10%, X5R, 0402"
D1: library part CMP-0079922-3, "LED, Red, SMD"
J1 J2 J4: library part CMP-0123041-2, "Conn Socket Strip SKT 10 POS 2.54mm Solder ST Top Entry Thru-Hole Bulk"
J3: library part CMP-0123022-2, "16 Position Receptacle Connector 0.100\" (2.54mm) Through Hole Tin"
L1: library part CMP-0003274-1, "Ferrite Bead, 10 ohm @ 100 MHz, 1.5 A, 0402"
LBL1: library part CMP-0003625-1, "Thermal Transfer Printable Labels, 0.650\" W x 0.200\" H - 10,000 per roll"
Logo1: library part CMP-0074844-1
Logo2: library part CMP-0074838-1, "Texas Instrument Corporate Signature"
Logo3: library part CMP-0074847-1, "FCC_disclaimer"
Logo4: library part CMP-0074769-1
R1 R11 R13 R19 R22 R27 R29: library part CMP-0026685-1, "RES, 2.40 k, 1%, 0.1 W, AEC-Q200 Grade 0, 0402"
R2 R3 R4 R5 R10 R15 R16 R17 R18 R23 R24 R26 R30: library part CMP-0078669-1, "RES, 10.0 k, 1%, 0.063 W, 0402"
R6: library part CMP-0026815-1, "RES, 100 k, 0.1%, 0.063 W, 0402"
R7 R8: library part CMP-0027004-2, "RES, 0, 5%, 0.063 W, 0402"
R9 R31: "RES, 56 k, 5%, 0.063 W, AEC-Q200 Grade 0, 0402"
R12 R20 R21 R28: library part CMP-0026722-1, "RES, 100, 1%, 0.063 W, 0402"
R14: "RES, 2.2 k, 5%, 0.063 W, AEC-Q200 Grade 0, 0402"
R25: library part CMP-0026725-1, "RES, 1.00 k, 1%, 0.0625 W, 0402"
S1: library part CMP-0002163-2, "Switch, Slide, SPST, Top Slide, SMT"
U1: library part CMP-0096487-1, "Real-Time Microcontrollers"
U2 U3: library part CMP-0084063-1, "10-MHz, Low-Noise, RRIO, CMOS Operational Amplifier for Cost-Sensitive Systems, DGK0008A (VSSOP-8)"
Y1: library part CMP-0093781-1, "20 MHz ?0ppm Crystal 8pF 50 Ohms 4-SMD, No Lead"

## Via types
v1: diameter 0.5, hole 0.3, Top Layer to Bottom Layer, tented both sides, 121 vias

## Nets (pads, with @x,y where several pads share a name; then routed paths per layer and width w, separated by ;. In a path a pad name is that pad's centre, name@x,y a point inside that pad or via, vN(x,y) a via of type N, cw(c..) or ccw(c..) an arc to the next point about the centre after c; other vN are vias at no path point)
3.3V: C6.1 C9.1 C10.1 C11.1 J3.1 J4.3 L1.1 R1.2 R2.2 R3.2 R4.2 R5.2 R9.2 R25.1 R31.2 U1.35 U1.46 | length 76.2
  Top Layer w0.3: 18.193,8.68 18.193,9.161 U1.35@18.935,9.904 ; U1.46@24.592,12.732 25.423,11.901 C11.1@26.7,11.901
  Top Layer w0.5: v1(6.7,19.352) v1(8.174,19.352) ; v1(8.4,5.3) 8.669,5.57 9.389,5.57 9.419,5.6 9.419,10.557 9.4,10.577 9.4,11.817 R9.2@9.435,11.852 v1(8.816,11.852) ; R31.2@12.55,7.4 12.55,6.637 v1(12.737,6.45) ; v1(13.936,18.388) L1.1@14.5,18.388 ; 18.193,8.68 19.05,7.824 19.05,6.85 C10.1@19.1,6.8 C9.1@19.1,5.366 19.1,4.308 19.393,4.015 v1(19.721,4.015) C6.1@20.65,4.015 20.65,2.734 21.1,2.284 J4.3@21.1,2 ; C11.1@26.7,11.901 26.8,11.901 26.85,11.951 26.85,12.407 27.243,12.8 v1(27.25,12.8) ; v1(27.25,14.501) 27.85,14.501 27.9,14.551 R5.2@27.9,14.6
  Bottom Layer w0.5: J3.1@1.98,23.39 3.295,22.075 5.255,22.075 6.7,20.631 v1(6.7,19.352) 6.7,18 8.816,15.884 v1(8.816,11.852) ; v1(8.174,19.352) 9.444,19.352 10.408,18.388 v1(13.936,18.388) ; v1(8.4,5.3) 11.587,5.3 13.887,7.6 v1(19.05,7.6) ; v1(19.721,4.015) 26.048,4.015 27.25,5.217 v1(27.25,14.501)
A1.65V: C16.1 C20.1 R10.2 R16.2 R20.2 R26.2 | length 37.1
  Top Layer w0.4: v1(6.565,22.75) 6.582,22.733 6.582,22.175 R10.2@6.6,22.158 ; v1(10.086,13.175) 10.094,13.184 10.583,13.184 R20.2@10.592,13.193 C16.1@11.799,13.193 ; v1(13.948,24.8) R16.2@14.6,24.8 ; R26.2@24.75,24.8 C20.1@26.15,24.8 26.165,24.785 26.165,24.216 v1(26.18,24.201)
  Bottom Layer w0.4: v1(10.086,13.175) 10.086,15.533 7.707,17.912 7.707,17.924 7.35,18.281 7.35,20.906 6.565,21.691 v1(6.565,22.75) 6.565,23.415 7.95,24.8 v1(13.948,24.8) 25.58,24.8 v1(26.18,24.201)
A3.3V: C8.1 C13.1 C21.1 L1.2 R18.2 U1.18 U2.8 U3.8 | length 20.9
  Top Layer w0.3: R18.2@6.6,17.063 7.313,17.063 7.702,17.451 8.972,17.451 8.977,17.456 10.248,17.456 ; U2.8@10.248,16.181 10.248,17.456 ; C13.1@11.85,17.046 11.838,17.034 11.79,17.082 11.225,17.082 10.851,17.456 10.248,17.456 ; C8.1@15.7,19.6 15.823,19.477 16.25,19.477 16.9,18.827 16.9,18.304 U1.18@17.521,17.682 ; C21.1@15.8,20.9 16.274,20.9 16.779,21.405 16.779,22.189 17.015,22.425 U3.8@17.425,22.425
  Top Layer w0.5: C13.1@11.85,17.046 v1(15.1,17.046) ; L1.2@14.5,19.588 14.511,19.6 v1(15.1,19.6) C8.1@15.7,19.6 15.7,20.85 15.75,20.9 C21.1@15.8,20.9
  Bottom Layer w0.5: v1(15.1,17.046) v1(15.1,19.6)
